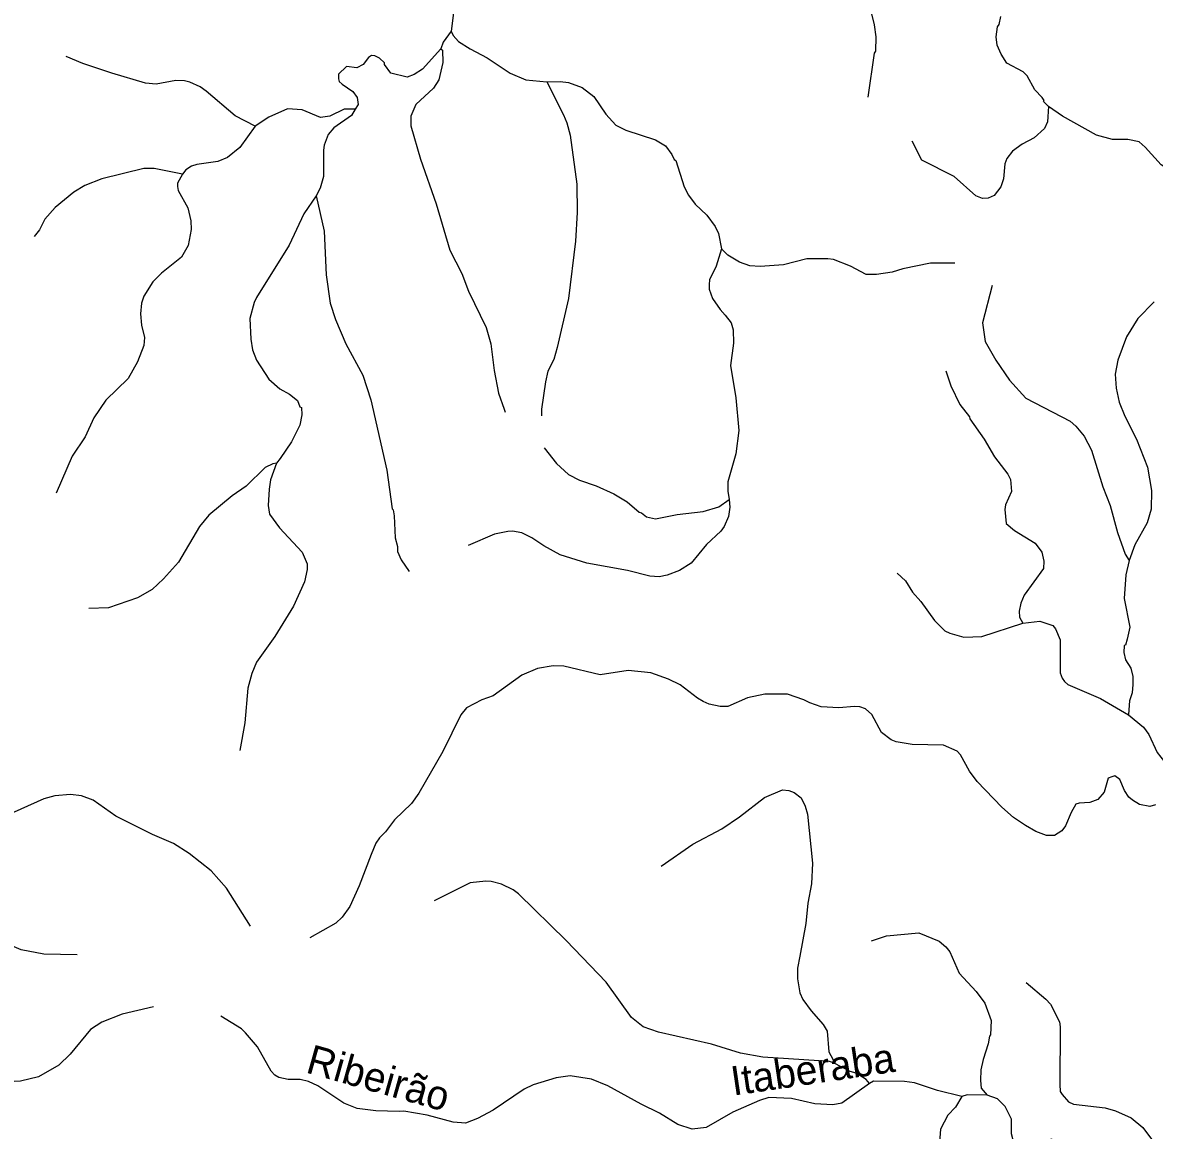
# Model space of a CAD drawing. Extents: x 346.5 to 372.4, y 7400.3 to 7428.2.
# Drawn here: x 356.096 to 359.198, y 7422.676 to 7425.713 of the extents above; entities that cross this region are included whole.
import ezdxf
from ezdxf.enums import TextEntityAlignment as Align

# ---------------------------------------------------------------- set-up
doc = ezdxf.new("R2010")
doc.units = 0
doc.header["$LTSCALE"] = 0.032
doc.layers.add('61', color=7, linetype='Continuous')
doc.layers.add('7', color=7, linetype='Continuous', lineweight=25)

msp = doc.modelspace()

# ---------------------------------------------------------------- linework, layer by layer
at = {"layer": '7'}
for points in [[(357.2041, 7425.9623), (357.2232, 7425.9017), (357.2519, 7425.8363), (357.2766, 7425.7694), (357.2782, 7425.7471), (357.2711, 7425.6895)], [(358.4195, 7425.7519), (358.4306, 7425.7072), (358.4346, 7425.6738), (358.4338, 7425.6347), (358.4306, 7425.6291), (358.4131, 7425.5088)], [(358.9083, 7425.4834), (358.8943, 7425.4973), (358.896, 7425.5), (358.8912, 7425.508), (358.8705, 7425.5287), (358.8498, 7425.567), (358.8387, 7425.5781), (358.794, 7425.602), (358.7789, 7425.6267), (358.7677, 7425.6514), (358.7653, 7425.6738), (358.7685, 7425.7016), (358.7733, 7425.708), (358.7773, 7425.7295)], [(357.2711, 7425.6895), (357.2495, 7425.6594), (357.2431, 7425.6417)], [(357.2711, 7425.6895), (357.2763, 7425.6774), (357.291, 7425.6618), (357.3229, 7425.6411), (357.3699, 7425.6164), (357.4329, 7425.5749), (357.4759, 7425.5566), (357.5329, 7425.5504)], [(357.2431, 7425.6417), (357.1922, 7425.5853), (357.1699, 7425.5709), (357.1507, 7425.5638), (357.1061, 7425.5741), (357.0886, 7425.598), (357.0886, 7425.6028), (357.0742, 7425.6156), (357.0615, 7425.6219), (357.0527, 7425.6227), (357.0447, 7425.6172), (357.0296, 7425.598), (357.0121, 7425.5893), (356.9842, 7425.5925), (356.9626, 7425.5718), (356.9618, 7425.559), (356.9642, 7425.5518), (356.9722, 7425.5446), (357.0017, 7425.5247), (357.0136, 7425.5079), (357.0161, 7425.4888), (357.0076, 7425.4759)], [(357.2431, 7425.6417), (357.247, 7425.6376), (357.248, 7425.6036), (357.2376, 7425.5566), (357.2225, 7425.5335), (357.1746, 7425.4889), (357.1603, 7425.4562), (357.1603, 7425.4299), (357.1874, 7425.339), (357.2296, 7425.2163), (357.2671, 7425.0888), (357.3005, 7425.025), (357.3189, 7424.9772), (357.3667, 7424.8768), (357.3802, 7424.8322), (357.389, 7424.7597), (357.401, 7424.6967), (357.4161, 7424.6537), (357.4193, 7424.6449)], [(356.7338, 7425.429), (356.6789, 7425.4578), (356.5993, 7425.5255), (356.5833, 7425.5367), (356.5546, 7425.5494), (356.5403, 7425.5534), (356.5164, 7425.5542), (356.4622, 7425.5446), (356.4335, 7425.547), (356.341, 7425.5741), (356.2613, 7425.6012), (356.2159, 7425.6204)], [(357.5329, 7425.5504), (357.5787, 7425.4602), (357.5882, 7425.4379), (357.597, 7425.4044), (357.6153, 7425.2705), (357.6161, 7425.1924), (357.6122, 7425.1143), (357.5922, 7424.9565), (357.5619, 7424.8226), (357.5524, 7424.7891), (357.5364, 7424.7573), (357.5293, 7424.7286), (357.5189, 7424.6537), (357.5189, 7424.6353)], [(357.5329, 7425.5504), (357.5699, 7425.5518), (357.5922, 7425.5486), (357.6297, 7425.5351), (357.6624, 7425.5104), (357.695, 7425.4618), (357.7221, 7425.4323), (357.75, 7425.4179), (357.8313, 7425.3916), (357.8584, 7425.3749), (357.8759, 7425.3518), (357.8823, 7425.3382), (357.8871, 7425.3351), (357.9094, 7425.2625), (357.9214, 7425.2402), (357.9397, 7425.2155), (357.9716, 7425.1852), (357.9947, 7425.1542), (358.0035, 7425.135), (358.0118, 7425.0926)], [(357.0076, 7425.4759), (356.9778, 7425.4761), (356.9387, 7425.4562), (356.9132, 7425.453), (356.8622, 7425.4737), (356.8224, 7425.4769), (356.7714, 7425.4538), (356.7338, 7425.429)], [(357.0076, 7425.4759), (356.9976, 7425.4584), (356.9491, 7425.4251), (356.9339, 7425.406), (356.9228, 7425.3773), (356.9212, 7425.363), (356.9212, 7425.2912), (356.9124, 7425.2596), (356.9011, 7425.2378)], [(358.9083, 7425.4834), (358.9056, 7425.4411), (358.8976, 7425.4227), (358.8689, 7425.3972), (358.8363, 7425.3797), (358.8092, 7425.3606), (358.794, 7425.3406), (358.7884, 7425.3263), (358.7853, 7425.2848), (358.7773, 7425.2625), (358.7598, 7425.2394), (358.743, 7425.2322), (358.7271, 7425.2306), (358.7088, 7425.2386), (358.6498, 7425.2912), (358.5613, 7425.3358), (358.5342, 7425.3877)], [(359.4802, 7425.1996), (359.4316, 7425.2235), (359.3965, 7425.2498), (359.3742, 7425.2625), (359.3407, 7425.2761), (359.2738, 7425.2952), (359.2276, 7425.3167), (359.2172, 7425.3231), (359.1734, 7425.3717), (359.1566, 7425.3861), (359.1256, 7425.3924), (359.0833, 7425.3924), (359.0395, 7425.4044), (358.9471, 7425.4562), (358.9083, 7425.4834)], [(356.7338, 7425.429), (356.6917, 7425.3709), (356.6582, 7425.343), (356.6311, 7425.3319), (356.5737, 7425.3239), (356.5594, 7425.3191), (356.5441, 7425.3092), (356.5347, 7425.2979)], [(356.5347, 7425.2979), (356.4574, 7425.3127), (356.4287, 7425.3135), (356.3139, 7425.2848), (356.2669, 7425.2665), (356.2366, 7425.2482), (356.1856, 7425.2059), (356.1577, 7425.1741), (356.1426, 7425.1454), (356.1283, 7425.1263)], [(356.5347, 7425.2979), (356.5211, 7425.2729), (356.5211, 7425.2641), (356.5227, 7425.253), (356.549, 7425.2052), (356.5578, 7425.1701), (356.5586, 7425.1462), (356.5498, 7425.1016), (356.5315, 7425.0697), (356.4773, 7425.0266), (356.4534, 7425.0027), (356.4287, 7424.9629), (356.4223, 7424.9438), (356.4191, 7424.9151), (356.4223, 7424.8832), (356.4303, 7424.8497), (356.4287, 7424.8274), (356.4112, 7424.7828), (356.3857, 7424.7373), (356.3243, 7424.6776), (356.2916, 7424.6298), (356.2677, 7424.5772), (356.2326, 7424.5246), (356.188, 7424.4233)], [(356.9011, 7425.2378), (356.867, 7425.1892), (356.8272, 7425.1031), (356.7379, 7424.9597), (356.7307, 7424.9454), (356.7188, 7424.9023), (356.722, 7424.8449), (356.7267, 7424.8162), (356.7371, 7424.7876), (356.7714, 7424.7357), (356.8017, 7424.7086), (356.8279, 7424.6943), (356.8495, 7424.6768), (356.8566, 7424.66), (356.8606, 7424.6577), (356.8614, 7424.6377), (356.8558, 7424.609), (356.8335, 7424.5636), (356.8025, 7424.5182), (356.7924, 7424.5049)], [(356.9011, 7425.2378), (356.9228, 7425.1414), (356.9284, 7425.0219), (356.9395, 7424.9438), (356.9539, 7424.8991), (356.9826, 7424.8322), (357.0288, 7424.7461), (357.0511, 7424.6792), (357.0949, 7424.4863), (357.1093, 7424.3803), (357.1125, 7424.3771), (357.1149, 7424.3604), (357.1173, 7424.3006), (357.1236, 7424.2767), (357.1244, 7424.2632), (357.134, 7424.24), (357.1563, 7424.2082)], [(358.0118, 7425.0926), (357.9971, 7425.0458), (357.9795, 7425.0075), (357.978, 7424.9948), (357.978, 7424.982), (357.9875, 7424.9565), (358.0082, 7424.927), (358.0218, 7424.9111), (358.0385, 7424.8904), (358.0441, 7424.8704), (358.0449, 7424.8338), (358.0369, 7424.7732), (358.0513, 7424.684), (358.0592, 7424.5947), (358.0513, 7424.5309), (358.0298, 7424.4544), (358.029, 7424.4289), (358.0334, 7424.4054)], [(358.6514, 7425.0537), (358.5852, 7425.0537), (358.5087, 7425.0378), (358.48, 7425.029), (358.437, 7425.0226), (358.4083, 7425.0226), (358.3653, 7425.0457), (358.3191, 7425.0633), (358.3031, 7425.0657), (358.2457, 7425.0657), (358.182, 7425.0489), (358.1182, 7425.0442), (358.0895, 7425.0465), (358.0616, 7425.0561), (358.0298, 7425.0752), (358.0118, 7425.0926)], [(358.7542, 7424.9924), (358.7271, 7424.8896), (358.735, 7424.8386), (358.7637, 7424.7876), (358.8012, 7424.7326), (358.8458, 7424.6831), (358.9678, 7424.6202), (358.9837, 7424.6066), (359.006, 7424.5788), (359.0259, 7424.5405), (359.057, 7424.4401), (359.0769, 7424.3891), (359.0977, 7424.3149), (359.1187, 7424.2557), (359.1293, 7424.2379)], [(359.1981, 7424.9477), (359.1534, 7424.9023), (359.1224, 7424.8513), (359.0985, 7424.7876), (359.0913, 7424.7493), (359.0937, 7424.711), (359.1024, 7424.6728), (359.1176, 7424.6345), (359.1495, 7424.5708), (359.1797, 7424.4943), (359.1909, 7424.4305), (359.1893, 7424.3795), (359.1789, 7424.3413), (359.1447, 7424.2815), (359.1293, 7424.2379)], [(358.6267, 7424.7581), (358.641, 7424.7174), (358.6657, 7424.6664), (358.692, 7424.6321), (358.6928, 7424.6266), (358.7319, 7424.5708), (358.7605, 7424.5222), (358.7972, 7424.4751), (358.8044, 7424.4608), (358.8068, 7424.4273), (358.7908, 7424.3907), (358.7884, 7424.3779), (358.7924, 7424.3397), (358.8148, 7424.3205), (358.8721, 7424.2855), (358.8897, 7424.2616), (358.8952, 7424.2361), (358.8944, 7424.2161), (358.8418, 7424.1436), (358.8323, 7424.1213), (358.8275, 7424.099), (358.8291, 7424.083), (358.838, 7424.0661)], [(357.5261, 7424.5477), (357.5596, 7424.5046), (357.593, 7424.4743), (357.6225, 7424.4584), (357.6688, 7424.4433), (357.7166, 7424.4209), (357.7532, 7424.3994), (357.7867, 7424.3707), (357.793, 7424.3691), (357.8066, 7424.358), (357.8313, 7424.3524), (357.8903, 7424.3644), (357.962, 7424.3731), (358.0051, 7424.3859), (358.0334, 7424.4054)], [(356.7924, 7424.5049), (356.782, 7424.5035), (356.761, 7424.4935), (356.7092, 7424.4417), (356.671, 7424.4154), (356.6064, 7424.3628), (356.5809, 7424.3317), (356.5235, 7424.2337), (356.4829, 7424.1882), (356.4518, 7424.1588), (356.4112, 7424.1356), (356.3315, 7424.1085), (356.2781, 7424.107)], [(356.7924, 7424.5049), (356.7762, 7424.4592), (356.7722, 7424.4337), (356.7698, 7424.3891), (356.773, 7424.3652), (356.8009, 7424.3277), (356.863, 7424.2616), (356.8766, 7424.2289), (356.8766, 7424.2138), (356.8686, 7424.1803), (356.8391, 7424.1133), (356.7873, 7424.0304), (356.7379, 7423.9595), (356.7251, 7423.9284), (356.714, 7423.8886), (356.7052, 7423.793), (356.6917, 7423.7173)], [(358.0334, 7424.4054), (358.0345, 7424.3843), (358.0313, 7424.3588), (358.0194, 7424.3317), (358.0098, 7424.3189), (357.9708, 7424.2823), (357.9286, 7424.2313), (357.8967, 7424.2105), (357.8632, 7424.1978), (357.8409, 7424.1938), (357.8154, 7424.1954), (357.7548, 7424.2113), (357.6432, 7424.2313), (357.5699, 7424.2536), (357.5253, 7424.2783), (357.4918, 7424.3006), (357.4647, 7424.3142), (357.4392, 7424.3189), (357.4265, 7424.3181), (357.3898, 7424.311), (357.3173, 7424.2791)], [(359.1293, 7424.2379), (359.12, 7424.1994), (359.116, 7424.1341), (359.1311, 7424.056), (359.124, 7424.0225), (359.1192, 7424.0065), (359.116, 7424.0049), (359.1144, 7423.9858), (359.1192, 7423.9659), (359.1343, 7423.9428), (359.1399, 7423.9205), (359.1399, 7423.8982), (359.1375, 7423.8758), (359.1303, 7423.8535), (359.1284, 7423.8291), (359.1279, 7423.8156)], [(358.4936, 7424.2034), (358.5167, 7424.1827), (358.5358, 7424.1516), (358.5581, 7424.1261), (358.5956, 7424.0735), (358.6243, 7424.0456), (358.6378, 7424.0392), (358.6761, 7424.0281), (358.7255, 7424.0296), (358.838, 7424.0661)], [(358.838, 7424.0661), (358.8849, 7424.0719), (358.9199, 7424.0599), (358.9271, 7424.0512), (358.9407, 7424.0209), (358.9407, 7423.93), (358.9454, 7423.9157), (358.9526, 7423.9069), (358.9614, 7423.8982), (359.0507, 7423.8599), (359.1279, 7423.8156)], [(359.2013, 7423.5682), (359.1861, 7423.5634), (359.1582, 7423.569), (359.1383, 7423.581), (359.1287, 7423.5897), (359.1168, 7423.6081), (359.104, 7423.6375), (359.0905, 7423.6479), (359.0817, 7423.6455), (359.0722, 7423.6415), (359.061, 7423.6033), (359.0435, 7423.5834), (359.022, 7423.5746), (358.9925, 7423.573), (358.9837, 7423.5698), (358.9701, 7423.5475), (358.955, 7423.5108), (358.9447, 7423.4973), (358.9247, 7423.4845), (358.9024, 7423.4845), (358.8737, 7423.4949), (358.845, 7423.5116), (358.8124, 7423.534), (358.7805, 7423.5618), (358.7127, 7423.632), (358.692, 7423.6607), (358.6673, 7423.7053), (358.6578, 7423.7156), (358.6203, 7423.7316), (358.5342, 7423.734), (358.4912, 7423.7412), (358.4769, 7423.7467), (358.4505, 7423.7667), (358.4242, 7423.8161), (358.4067, 7423.8312), (358.3908, 7423.8368), (358.3764, 7423.8376), (358.3334, 7423.8344), (358.2856, 7423.8368), (358.2537, 7423.8479), (358.2378, 7423.8567), (358.1931, 7423.8718), (358.131, 7423.8718), (358.0832, 7423.8615), (358.029, 7423.8384), (358.0083, 7423.8376), (357.978, 7423.8448), (357.962, 7423.8519), (357.9461, 7423.8607), (357.8983, 7423.8974), (357.8664, 7423.9133), (357.8186, 7423.93), (357.7564, 7423.9364), (357.6799, 7423.9252), (357.5795, 7423.9484), (357.5508, 7423.9492), (357.5078, 7423.942), (357.4647, 7423.9236), (357.3866, 7423.8671), (357.3548, 7423.8567), (357.3133, 7423.8344), (357.2974, 7423.8153), (357.2479, 7423.7149), (357.1826, 7423.6001), (357.1619, 7423.5722), (357.1157, 7423.5276), (357.0909, 7423.4941), (357.075, 7423.4782), (357.0646, 7423.463), (357.0519, 7423.4327), (357.0192, 7423.3467), (356.9937, 7423.2893), (356.9722, 7423.2606), (356.9547, 7423.2439), (356.8838, 7423.204)], [(359.1279, 7423.8156), (359.1686, 7423.7818), (359.1829, 7423.7611), (359.206, 7423.7117), (359.226, 7423.6862), (359.2491, 7423.6662), (359.2874, 7423.6422)], [(357.8465, 7423.4001), (357.9333, 7423.4606), (358.013, 7423.5029), (358.0616, 7423.5355), (358.1302, 7423.5889), (358.1788, 7423.6097), (358.1963, 7423.6081), (358.2115, 7423.6025), (358.2306, 7423.5874), (358.2417, 7423.565), (358.2481, 7423.5427), (358.2617, 7423.4088), (358.2585, 7423.3515), (358.2489, 7423.2989), (358.2433, 7423.2431), (358.2266, 7423.1538), (358.2202, 7423.1203), (358.2202, 7423.0917), (358.2266, 7423.0534), (358.2354, 7423.0343), (358.2577, 7423.004), (358.2911, 7422.9665), (358.3015, 7422.9474), (358.3063, 7422.8908), (358.3169, 7422.8713), (358.319, 7422.861)], [(356.7212, 7423.2359), (356.655, 7423.3403), (356.6136, 7423.3873), (356.553, 7423.4351), (356.51, 7423.4622), (356.4526, 7423.4869), (356.3522, 7423.5371), (356.29, 7423.581), (356.2582, 7423.5929), (356.2279, 7423.5969), (356.1848, 7423.5929), (356.1546, 7423.5849), (356.047, 7423.5363), (355.9959, 7423.4989), (355.941, 7423.4471), (355.8453, 7423.3387), (355.8294, 7423.31), (355.823, 7423.2885), (355.8229, 7423.2526)], [(358.319, 7422.861), (358.3077, 7422.8644), (358.1257, 7422.8764), (358.064, 7422.8876), (357.9843, 7422.9123), (357.8393, 7422.945), (357.7971, 7422.9593), (357.7652, 7422.9856), (357.6958, 7423.0821), (357.5866, 7423.1961), (357.4552, 7423.3244), (357.4408, 7423.3355), (357.4089, 7423.3506), (357.3803, 7423.3586), (357.3659, 7423.3594), (357.3229, 7423.3546), (357.2249, 7423.3052)], [(356.2462, 7423.157), (356.1546, 7423.1586), (356.0924, 7423.1705), (356.0541, 7423.1873), (355.9776, 7423.2391), (355.9298, 7423.263), (355.8836, 7423.267), (355.8229, 7423.2526)], [(358.4235, 7423.1953), (358.4641, 7423.2096), (358.5533, 7423.2176), (358.6091, 7423.1945), (358.6267, 7423.1793), (358.6378, 7423.165), (358.6633, 7423.1068), (358.7103, 7423.0566), (358.7335, 7423.0247), (358.751, 7422.9769), (358.7494, 7422.9378), (358.7462, 7422.9346), (358.743, 7422.9131), (358.7295, 7422.8701), (358.7231, 7422.8414), (358.7215, 7422.8127), (358.7239, 7422.792), (358.7398, 7422.7726)], [(358.8474, 7423.0813), (358.9008, 7423.0359), (358.9136, 7423.0215), (358.9383, 7422.9737), (358.9407, 7422.9594), (358.9391, 7422.8016), (358.9407, 7422.7824), (358.9454, 7422.7745), (358.963, 7422.7545), (358.9773, 7422.7474), (359.0634, 7422.7378), (359.0921, 7422.729), (359.1351, 7422.7099), (359.167, 7422.6836), (359.1957, 7422.6446), (359.1989, 7422.6055), (359.1901, 7422.5434), (359.1722, 7422.469), (359.174, 7422.4223)], [(356.455, 7423.0143), (356.3697, 7422.9944), (356.3139, 7422.9729), (356.2821, 7422.9522), (356.2263, 7422.8852), (356.196, 7422.8549), (356.1402, 7422.8231), (356.0908, 7422.8111), (356.0733, 7422.8095), (356.0302, 7422.8127), (355.9553, 7422.8255), (355.7704, 7422.8804), (355.7199, 7422.903), (355.7027, 7422.9147)], [(358.4178, 7422.8046), (358.3414, 7422.7505), (358.3175, 7422.7458), (358.2681, 7422.749), (358.2043, 7422.7633), (358.1421, 7422.7657), (358.1166, 7422.7577), (358.0433, 7422.7258), (357.97, 7422.6836), (357.9317, 7422.6788), (357.8927, 7422.6924), (357.8425, 7422.7234), (357.7915, 7422.7474), (357.7006, 7422.7984), (357.656, 7422.8159), (357.597, 7422.8255), (357.5588, 7422.8199), (357.4958, 7422.8008), (357.4711, 7422.7888), (357.3866, 7422.7314), (357.3436, 7422.7083), (357.3101, 7422.6956), (357.2767, 7422.6979), (357.2049, 7422.7179), (357.1412, 7422.7282), (357.1284, 7422.7274), (357.0647, 7422.729), (357.0137, 7422.7354), (356.977, 7422.7505), (356.9053, 7422.7976), (356.8798, 7422.8095), (356.8575, 7422.8151), (356.824, 7422.8151), (356.7985, 7422.8207), (356.7873, 7422.8271), (356.7777, 7422.8382), (356.7403, 7422.9052), (356.7076, 7422.9434), (356.6965, 7422.9538), (356.6399, 7422.9888)], [(358.4178, 7422.8046), (358.4085, 7422.8151), (358.3813, 7422.8327), (358.3648, 7422.8375), (358.319, 7422.861)], [(358.6712, 7422.7687), (358.6044, 7422.7848), (358.5406, 7422.8063), (358.5135, 7422.8095), (358.4288, 7422.8108), (358.4178, 7422.8046)], [(358.7398, 7422.7726), (358.685, 7422.7735), (358.6712, 7422.7687)], [(359.174, 7422.4223), (359.152, 7422.4574), (359.1415, 7422.4908), (359.1367, 7422.533), (359.116, 7422.5664), (359.0953, 7422.5784), (359.0793, 7422.5832), (359.0331, 7422.5912), (359.0188, 7422.588), (358.9933, 7422.5943), (358.9797, 7422.6007), (358.9407, 7422.6406), (358.9168, 7422.6517), (358.8945, 7422.6453), (358.8602, 7422.6278), (358.8371, 7422.631), (358.8211, 7422.6398), (358.8179, 7422.6462), (358.8115, 7422.6493), (358.8068, 7422.6661), (358.8068, 7422.7067), (358.7892, 7422.741), (358.7685, 7422.7625), (358.7398, 7422.7726)], [(358.6712, 7422.7687), (358.6538, 7422.7394), (358.6322, 7422.7171), (358.6123, 7422.6788), (358.602, 7422.5481), (358.5868, 7422.5099), (358.5709, 7422.4868), (358.5366, 7422.4605), (358.504, 7422.4437), (358.429, 7422.4206), (358.3908, 7422.4063), (358.3653, 7422.3927), (358.3398, 7422.368), (358.2864, 7422.2979), (358.2274, 7422.2501)]]:
    msp.add_lwpolyline(points, dxfattribs=at)

# ---------------------------------------------------------------- texts
at = {"layer": '61'}
for s, rotation, p in [('Ribeirão', 344.224, (357.0611, 7422.7811)), ('Itaberaba', 8.413, (358.2676, 7422.804))]:
    msp.add_text(s, height=0.08, rotation=rotation, dxfattribs=at).set_placement(p, align=Align.CENTER)

doc.saveas('drawing.dxf')
